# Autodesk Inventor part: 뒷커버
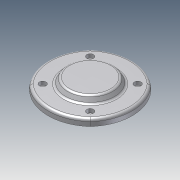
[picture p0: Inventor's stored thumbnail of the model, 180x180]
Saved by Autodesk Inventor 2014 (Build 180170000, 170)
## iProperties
Company: 한국ATC센터
Created: 2014-08
Part Number: 뒷커버
Document SubType Name: Modeling
Designer: KYOUNG IL JANG
Density: 1 g/cm^3
Material: 일반
Appearance: 기본값
Mass: 95.9792 g
Surface Area: 228.849 cm^2
Volume: 95.9792 cm^3
Author: KYOUNG IL JANG
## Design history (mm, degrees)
sketch "스케치1"
  geometry: C1 r 30 at (0, 0) reference; A1 r 53.623 centre (0, -3.623) between (36.062, 36.062) and (-36.062, 36.062) reference; A2 r 53.623 centre (3.623, 0) between (-36.062, 36.062) and (-36.062, -36.062) reference; A3 r 53.623 centre (-3.623, 0) between (36.062, -36.062) and (36.062, 36.062) reference; A4 r 53.623 centre (0, 3.623) between (-36.062, -36.062) and (36.062, -36.062) reference; 1 further point
  node "참조9"
  node "참조14"
  node "참조15"
  node "참조16"
  node "참조17"
extrude "돌출1" new body sketch "스케치1" distance "d0" = 8; taper "d1" = 0 deg
sketch "스케치2"
  geometry: C1 r 30 at (0, 0); 1 further point
  constraints: 1 centre point, 1 coincident
  dimensions: "d2" = 60 diameter of C1
extrude "돌출2" join sketch "스케치2" distance "d3" = 7; taper "d4" = -30 deg
sketch "스케치3"
  geometry: C1 r 1.621 at (28.284, 28.284) reference; C2 r 1.621 at (-28.284, 28.284) reference; C3 r 1.621 at (-28.284, -28.284) reference; C4 r 1.621 at (28.284, -28.284) reference; 1 further point
hole "구멍2" sketch "스케치3" at (-28.284, -28.284), (-28.284, 28.284), (28.284, 28.284), (28.284, -28.284) diameter "d14" = 4.5; stored, may be unused: countersink angle "d18" = 90 deg, drill point angle "d20" = 118 deg; dims "d15" = 6, "d16" = 8, "d17" = 4.4, "d19" = 20
extrude "돌출3" join sketch "스케치1" distance "d21" = 12; taper "d22" = 0 deg
hole "구멍3" diameter "d25" = 30; stored, may be unused: countersink angle "d29" = 90 deg, drill point angle "d31" = 0 deg; dims "d23" = 10, "d24" = 10, "d26" = 6, "d27" = 40, "d28" = 12, "d30" = 15
fillet "모깎기1" dims "d32" = 3, "d33" = 0.3
chamfer "모따기1" distance "d34" = 1; stored, may be unused: second distance "d35" = 2, angle "d36" = 45 deg
node "솔리드1"
node "참조18"
node "참조19"
node "참조20"
node "참조21"
